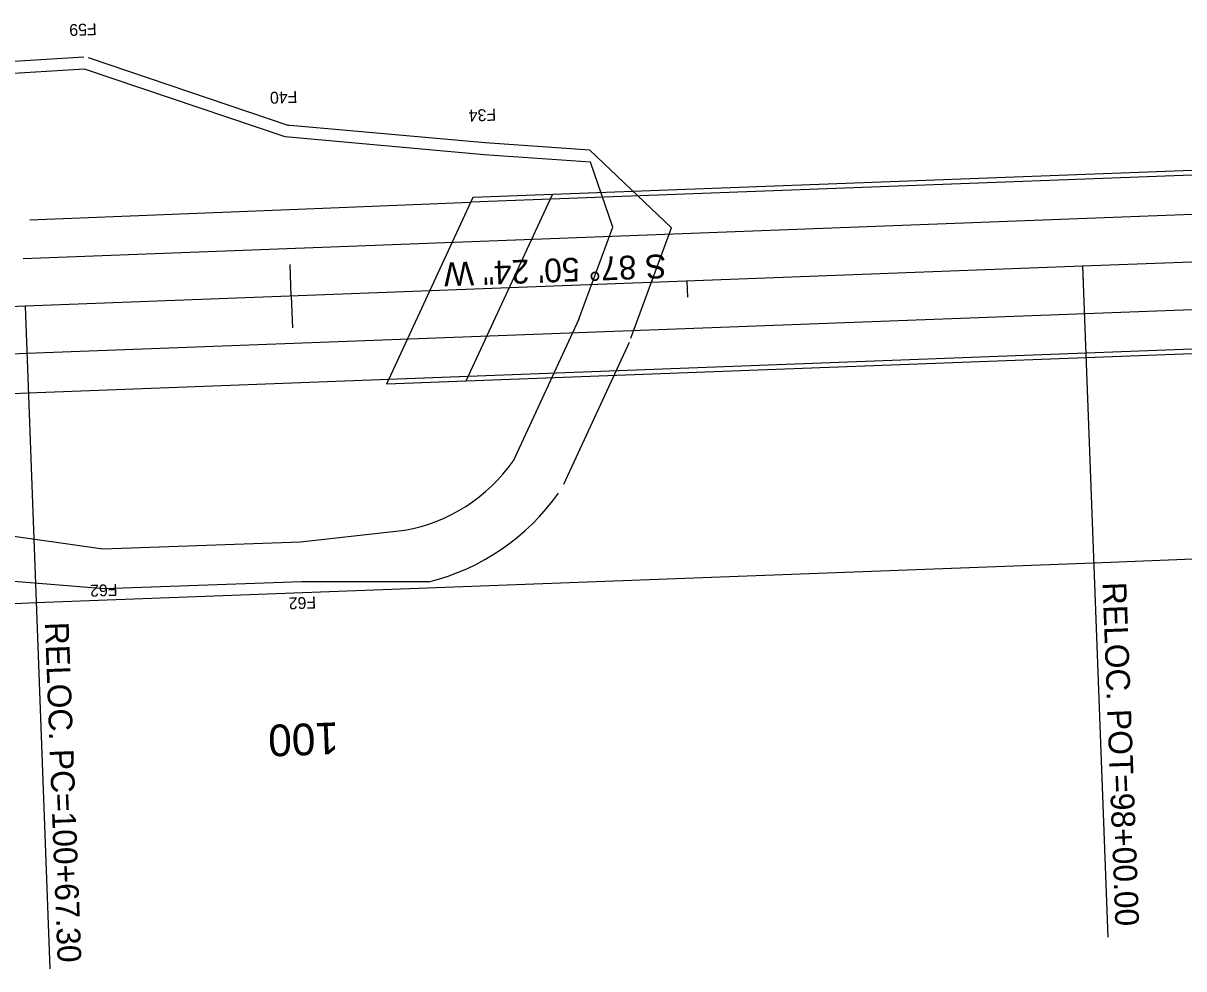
# Model space of a CAD drawing. Extents: x 1475170 to 1480100, y 1103245 to 1119475.
# Drawn here: x 1476777 to 1477070.1, y 1111127.6 to 1111366.5 of the extents above; entities that cross this region are included whole.
import ezdxf

# ---------------------------------------------------------------- set-up
doc = ezdxf.new("R2010")
doc.units = 0
for name, color, linetype in [('RD_HC_CL_Rel', 7, 'Continuous'), ('RD_HC_Data_Rel', 7, 'Continuous'), ('RD_HC_Data_Tic_Rel', 7, 'Continuous'), ('RD_HC_TX_Rel_Sta50', 7, 'Continuous'), ('RD_PD_Bridge', 7, 'Continuous'), ('RD_PD_CstnLmt', 7, 'Continuous'), ('RD_PD_CstnLmt_TX', 7, 'Continuous'), ('RD_PD_DR_ErosCtrl', 7, 'Continuous'), ('RD_PD_Final_TrvlWay', 7, 'Continuous'), ('RD_PD_GR', 7, 'Continuous'), ('RD_PD_RW', 7, 'Continuous')]:
    doc.layers.add(name, color=color, linetype=linetype)

msp = doc.modelspace()

# ---------------------------------------------------------------- linework, layer by layer
at = {"layer": 'RD_HC_CL_Rel'}
for p, q in [((1477244.45, 1111312.61), (1477044.6, 1111305.07)), ((1477044.6, 1111305.07), (1476777.49, 1111295))]:
    msp.add_line(p, q, dxfattribs=at)
msp.add_arc((1476845.33, 1109496.28), 1800, 92.16, 112.05197, dxfattribs=at)
at = {"layer": 'RD_HC_Data_Rel'}
for p, q in [((1477044.6, 1111305.07), (1477050.99, 1111135.61)), ((1476777.49, 1111295), (1476783.8, 1111127.64))]:
    msp.add_line(p, q, dxfattribs=at)
at = {"layer": 'RD_HC_Data_Tic_Rel'}
for p, q in [((1476844.74, 1111297.54), (1476844.44, 1111305.53)), ((1477044.6, 1111305.07), (1477044.75, 1111301.08)), ((1476944.67, 1111301.31), (1476944.82, 1111297.31)), ((1476844.74, 1111297.54), (1476845.04, 1111289.54))]:
    msp.add_line(p, q, dxfattribs=at)
at = {"layer": 'RD_PD_Bridge'}
for p, q in [((1477219.85, 1111333.7), (1476890.09, 1111321.26)), ((1477220.38, 1111334.85), (1476890.62, 1111322.41)), ((1476890.62, 1111322.41), (1476868.81, 1111275.3)), ((1476910.6, 1111323.16), (1476888.8, 1111276.06)), ((1477199.11, 1111288.89), (1476869.34, 1111276.45)), ((1477198.58, 1111287.74), (1476868.81, 1111275.3))]:
    msp.add_line(p, q, dxfattribs=at)
at = {"layer": 'RD_PD_CstnLmt'}
for p, q in [((1476792.54, 1111354.86), (1476741.56, 1111351.77)), ((1476843.22, 1111337.75), (1476792.54, 1111354.86)), ((1476893.43, 1111333.25), (1476843.22, 1111337.75)), ((1476917.36, 1111291.71), (1476900.77, 1111255.86)), ((1476797.11, 1111233.59), (1476747.77, 1111240.68)), ((1476873.45, 1111238.38), (1476847.08, 1111235.39)), ((1476847.08, 1111235.39), (1476797.11, 1111233.59))]:
    msp.add_line(p, q, dxfattribs=at)
msp.add_lwpolyline([(1476917.36, 1111291.71), (1476925.92, 1111314.95), (1476920.3, 1111331.38), (1476893.43, 1111333.25)], dxfattribs=at)
msp.add_arc((1476865.74, 1111280.52), 42.83, 280.3678, 324.8604, dxfattribs=at)
at = {"layer": 'RD_PD_DR_ErosCtrl'}
for p, q in [((1476792.36, 1111357.86), (1476741.38, 1111354.77)), ((1476844.18, 1111340.59), (1476793.5, 1111357.7)), ((1476893.7, 1111336.24), (1476843.49, 1111340.74)), ((1476930.07, 1111285.83), (1476913.47, 1111249.98)), ((1476797.47, 1111223.6), (1476745.92, 1111227.82)), ((1476847.44, 1111225.39), (1476797.47, 1111223.6)), ((1476879.48, 1111225.37), (1476847.44, 1111225.39))]:
    msp.add_line(p, q, dxfattribs=at)
msp.add_lwpolyline([(1476930.5, 1111286.88), (1476940.77, 1111314.78), (1476920.18, 1111334.38), (1476893.7, 1111336.24)], dxfattribs=at)
msp.add_arc((1476865.74, 1111280.52), 56.83, 283.9872, 324.8604, dxfattribs=at)
at = {"layer": 'RD_PD_Final_TrvlWay'}
for p, q in [((1477244, 1111324.6), (1476777.04, 1111306.99)), ((1477244.91, 1111300.62), (1476777.94, 1111283.01))]:
    msp.add_line(p, q, dxfattribs=at)
msp.add_arc((1476845.33, 1109496.28), 1788, 92.16, 112.05197, dxfattribs=at)
at = {"layer": 'RD_PD_GR'}
for p, q in [((1476850.62, 1111319.69), (1476890.09, 1111321.26)), ((1476778.67, 1111316.82), (1476850.62, 1111319.69)), ((1476889.33, 1111277.2), (1476778.32, 1111273.02))]:
    msp.add_line(p, q, dxfattribs=at)
msp.add_arc((1476845.33, 1109496.28), 1778, 92.16, 112.05197, dxfattribs=at)
at = {"layer": 'RD_PD_RW'}
for p, q in [((1477247.28, 1111237.67), (1477047.42, 1111230.13)), ((1477047.42, 1111230.13), (1476780.31, 1111220.05))]:
    msp.add_line(p, q, dxfattribs=at)
msp.add_arc((1476845.33, 1109496.28), 1725, 92.16, 97.97556, dxfattribs=at)

# ---------------------------------------------------------------- texts
at = {"layer": 'RD_HC_Data_Rel'}
for s, rotation, p in [('S 87%%d 50\' 24" W', 182.16, (1476939.34, 1111308.11)), ('RELOC. POT=98+00.00', 272.16, (1477049.61, 1111225.21)), ('RELOC. PC=100+67.30', 272.16, (1476782.5, 1111215.13))]:
    msp.add_text(s, height=6, rotation=rotation, dxfattribs=at).set_placement(p)
at = {"layer": 'RD_HC_TX_Rel_Sta50'}
msp.add_text('100', height=8, rotation=182.16, dxfattribs=at).set_placement((1476856.6, 1111189.91))
at = {"layer": 'RD_PD_CstnLmt_TX'}
for s, p in [('F59', (1476795.53, 1111366.48)), ('F40', (1476846.21, 1111349.37)), ('F34', (1476896.42, 1111344.87)), ('F62', (1476800.79, 1111224.86)), ('F62', (1476850.95, 1111221.66))]:
    msp.add_text(s, height=3, rotation=182.16, dxfattribs=at).set_placement(p)

doc.saveas('drawing.dxf')
